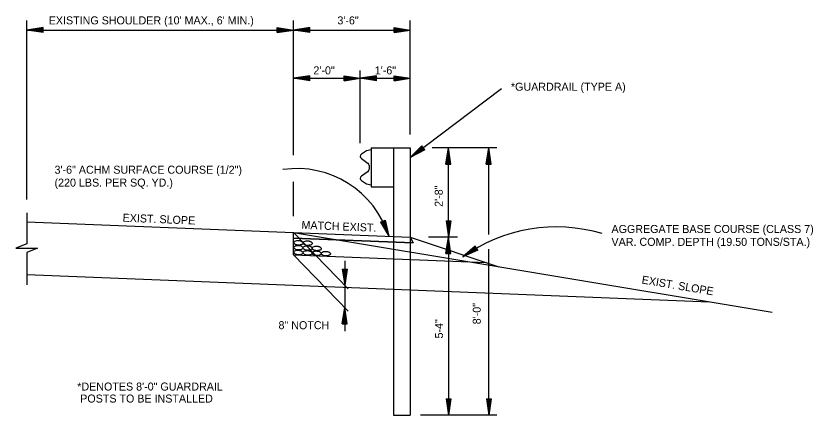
# Model space of a CAD drawing. Extents: x 1374136 to 1374281, y 380549 to 380948.
# Drawn here: x 1374137.7 to 1374197.5, y 380742 to 380771.9 of the extents above; entities that cross this region are included whole.
import ezdxf

# ---------------------------------------------------------------- set-up
doc = ezdxf.new("R2010")
doc.units = 0
for name, color, linetype in [('C-ANNO-TEXT', 7, 'Continuous'), ('Default', 7, 'Continuous'), ('R_Draft', 7, 'Continuous')]:
    doc.layers.add(name, color=color, linetype=linetype)

msp = doc.modelspace()

# ---------------------------------------------------------------- linework, layer by layer
at = {"layer": 'C-ANNO-TEXT'}
msp.add_lwpolyline([(1374138.56, 380757.182), (1374138.56, 380754.852), (1374137.749, 380754.528), (1374139.371, 380754.528), (1374138.56, 380754.205), (1374138.56, 380751.78)], dxfattribs=at)
at = {"layer": 'Default'}
for p, q in [((1374138.56, 380758.166), (1374138.56, 380771.592)), ((1374139.777, 380771.05), (1374138.56, 380770.867)), ((1374139.777, 380770.684), (1374139.777, 380771.05)), ((1374157.342, 380770.684), (1374157.343, 380771.05)), ((1374157.343, 380771.05), (1374158.56, 380770.867)), ((1374158.56, 380761.489), (1374158.56, 380771.592)), ((1374159.777, 380771.05), (1374158.56, 380770.867)), ((1374159.777, 380770.684), (1374159.777, 380771.05)), ((1374166.092, 380770.684), (1374166.093, 380771.05)), ((1374166.093, 380771.05), (1374167.31, 380770.867)), ((1374167.31, 380763.044), (1374167.31, 380771.592)), ((1374138.56, 380770.867), (1374158.56, 380770.867)), ((1374139.777, 380770.684), (1374138.56, 380770.867)), ((1374139.777, 380771.019), (1374138.764, 380770.867)), ((1374139.777, 380770.715), (1374138.764, 380770.867)), ((1374139.777, 380770.987), (1374138.973, 380770.867)), ((1374139.777, 380770.747), (1374138.973, 380770.867)), ((1374139.777, 380770.958), (1374139.177, 380770.868)), ((1374139.777, 380770.776), (1374139.177, 380770.868)), ((1374139.777, 380770.927), (1374139.381, 380770.868)), ((1374139.777, 380770.807), (1374139.381, 380770.868)), ((1374139.777, 380770.895), (1374139.585, 380770.868)), ((1374139.777, 380770.839), (1374139.585, 380770.868)), ((1374157.342, 380770.927), (1374157.739, 380770.868)), ((1374157.342, 380770.895), (1374157.534, 380770.868)), ((1374157.342, 380770.807), (1374157.739, 380770.868)), ((1374157.342, 380770.776), (1374157.943, 380770.868)), ((1374157.342, 380770.839), (1374157.534, 380770.868)), ((1374157.342, 380770.684), (1374158.56, 380770.867)), ((1374157.342, 380770.747), (1374158.147, 380770.867)), ((1374157.342, 380770.715), (1374158.356, 380770.867)), ((1374157.343, 380771.019), (1374158.356, 380770.867)), ((1374157.343, 380770.987), (1374158.147, 380770.867)), ((1374157.343, 380770.958), (1374157.943, 380770.868)), ((1374158.56, 380770.867), (1374167.31, 380770.867)), ((1374159.777, 380770.684), (1374158.56, 380770.867)), ((1374159.777, 380771.019), (1374158.764, 380770.867)), ((1374159.777, 380770.715), (1374158.764, 380770.867)), ((1374159.777, 380770.987), (1374158.973, 380770.867)), ((1374159.777, 380770.747), (1374158.973, 380770.867)), ((1374159.777, 380770.958), (1374159.177, 380770.868)), ((1374159.777, 380770.776), (1374159.177, 380770.868)), ((1374159.777, 380770.927), (1374159.381, 380770.868)), ((1374159.777, 380770.807), (1374159.381, 380770.868)), ((1374159.777, 380770.895), (1374159.585, 380770.868)), ((1374159.777, 380770.839), (1374159.585, 380770.868)), ((1374166.092, 380770.927), (1374166.489, 380770.868)), ((1374166.092, 380770.895), (1374166.284, 380770.868)), ((1374166.092, 380770.807), (1374166.489, 380770.868)), ((1374166.092, 380770.776), (1374166.693, 380770.868)), ((1374166.092, 380770.839), (1374166.284, 380770.868)), ((1374166.092, 380770.684), (1374167.31, 380770.867)), ((1374166.092, 380770.747), (1374166.897, 380770.867)), ((1374166.092, 380770.715), (1374167.106, 380770.867)), ((1374166.093, 380771.019), (1374167.106, 380770.867)), ((1374166.093, 380770.987), (1374166.897, 380770.867)), ((1374166.093, 380770.958), (1374166.693, 380770.868)), ((1374163.56, 380762.404), (1374163.56, 380767.848)), ((1374159.777, 380767.439), (1374158.56, 380767.256)), ((1374158.56, 380767.256), (1374163.56, 380767.256)), ((1374159.777, 380767.073), (1374158.56, 380767.256)), ((1374159.777, 380767.408), (1374158.764, 380767.256)), ((1374159.777, 380767.104), (1374158.764, 380767.256)), ((1374159.777, 380767.376), (1374158.973, 380767.256)), ((1374159.777, 380767.136), (1374158.973, 380767.256)), ((1374159.777, 380767.347), (1374159.177, 380767.257)), ((1374159.777, 380767.165), (1374159.177, 380767.257)), ((1374159.777, 380767.316), (1374159.381, 380767.257)), ((1374159.777, 380767.196), (1374159.381, 380767.257)), ((1374159.777, 380767.284), (1374159.585, 380767.257)), ((1374159.777, 380767.228), (1374159.585, 380767.257)), ((1374159.777, 380767.073), (1374159.777, 380767.439)), ((1374162.342, 380767.073), (1374162.343, 380767.439)), ((1374162.342, 380767.316), (1374162.739, 380767.257)), ((1374162.342, 380767.284), (1374162.534, 380767.257)), ((1374162.342, 380767.196), (1374162.739, 380767.257)), ((1374162.342, 380767.165), (1374162.943, 380767.257)), ((1374162.342, 380767.228), (1374162.534, 380767.257)), ((1374162.342, 380767.073), (1374163.56, 380767.256)), ((1374162.342, 380767.136), (1374163.147, 380767.256)), ((1374162.342, 380767.104), (1374163.356, 380767.256)), ((1374162.343, 380767.439), (1374163.56, 380767.256)), ((1374162.343, 380767.408), (1374163.356, 380767.256)), ((1374162.343, 380767.376), (1374163.147, 380767.256)), ((1374162.343, 380767.347), (1374162.943, 380767.257)), ((1374164.777, 380767.439), (1374163.56, 380767.256)), ((1374163.56, 380767.256), (1374167.31, 380767.256)), ((1374164.777, 380767.073), (1374163.56, 380767.256)), ((1374164.777, 380767.408), (1374163.764, 380767.256)), ((1374164.777, 380767.104), (1374163.764, 380767.256)), ((1374164.777, 380767.376), (1374163.973, 380767.256)), ((1374164.777, 380767.136), (1374163.973, 380767.256)), ((1374164.777, 380767.347), (1374164.177, 380767.257)), ((1374164.777, 380767.165), (1374164.177, 380767.257)), ((1374164.777, 380767.316), (1374164.381, 380767.257)), ((1374164.777, 380767.196), (1374164.381, 380767.257)), ((1374164.777, 380767.284), (1374164.585, 380767.257)), ((1374164.777, 380767.228), (1374164.585, 380767.257)), ((1374164.777, 380767.073), (1374164.777, 380767.439)), ((1374166.092, 380767.073), (1374166.093, 380767.439)), ((1374166.092, 380767.316), (1374166.489, 380767.257)), ((1374166.092, 380767.284), (1374166.284, 380767.257)), ((1374166.092, 380767.196), (1374166.489, 380767.257)), ((1374166.092, 380767.165), (1374166.693, 380767.257)), ((1374166.092, 380767.228), (1374166.284, 380767.257)), ((1374166.092, 380767.073), (1374167.31, 380767.256)), ((1374166.092, 380767.136), (1374166.897, 380767.256)), ((1374166.092, 380767.104), (1374167.106, 380767.256)), ((1374166.093, 380767.439), (1374167.31, 380767.256)), ((1374166.093, 380767.408), (1374167.106, 380767.256)), ((1374166.093, 380767.376), (1374166.897, 380767.256)), ((1374166.093, 380767.347), (1374166.693, 380767.257)), ((1374167.31, 380761.317), (1374174.155, 380766.49)), ((1374168.172, 380762.195), (1374167.31, 380761.317)), ((1374168.193, 380762.172), (1374167.471, 380761.437)), ((1374168.213, 380762.144), (1374167.644, 380761.57)), ((1374168.226, 380762.119), (1374167.804, 380761.69)), ((1374168.246, 380762.099), (1374167.965, 380761.813)), ((1374168.39, 380761.907), (1374168.172, 380762.195)), ((1374164.021, 380761.815), (1374163.645, 380761.563)), ((1374164.385, 380761.886), (1374164.021, 380761.815)), ((1374164.385, 380762.044), (1374167.31, 380762.044)), ((1374164.385, 380762.044), (1374164.385, 380759.119)), ((1374166.06, 380762.044), (1374166.06, 380742.028)), ((1374167.31, 380762.044), (1374167.31, 380742.028)), ((1374168.39, 380761.907), (1374167.31, 380761.317)), ((1374168.374, 380761.929), (1374167.471, 380761.437)), ((1374168.352, 380761.955), (1374167.644, 380761.57)), ((1374168.334, 380761.98), (1374167.804, 380761.69)), ((1374168.313, 380762.006), (1374167.965, 380761.813)), ((1374168.264, 380762.073), (1374168.129, 380761.937)), ((1374168.3, 380762.033), (1374168.129, 380761.937)), ((1374173.788, 380762.044), (1374168.949, 380762.044)), ((1374169.984, 380760.827), (1374170.167, 380762.044)), ((1374170.011, 380760.826), (1374170.165, 380761.842)), ((1374170.045, 380760.828), (1374170.166, 380761.625)), ((1374170.315, 380760.823), (1374170.165, 380761.842)), ((1374170.28, 380760.824), (1374170.166, 380761.625)), ((1374170.167, 380755.353), (1374170.167, 380762.044)), ((1374170.345, 380760.826), (1374170.167, 380762.044)), ((1374173.007, 380760.827), (1374173.19, 380762.044)), ((1374173.034, 380760.826), (1374173.188, 380761.842)), ((1374173.068, 380760.828), (1374173.189, 380761.625)), ((1374173.338, 380760.823), (1374173.188, 380761.842)), ((1374173.303, 380760.824), (1374173.189, 380761.625)), ((1374173.368, 380760.826), (1374173.19, 380762.044)), ((1374173.19, 380755.548), (1374173.19, 380762.044)), ((1374163.642, 380761.243), (1374164.154, 380760.884)), ((1374170.076, 380760.827), (1374170.165, 380761.425)), ((1374170.109, 380760.828), (1374170.166, 380761.222)), ((1374170.139, 380760.822), (1374170.165, 380761.017)), ((1374170.252, 380760.829), (1374170.165, 380761.425)), ((1374170.192, 380760.827), (1374170.165, 380761.017)), ((1374170.224, 380760.825), (1374170.166, 380761.222)), ((1374173.099, 380760.827), (1374173.189, 380761.425)), ((1374173.133, 380760.828), (1374173.189, 380761.222)), ((1374173.162, 380760.822), (1374173.189, 380761.017)), ((1374173.275, 380760.829), (1374173.189, 380761.425)), ((1374173.248, 380760.825), (1374173.189, 380761.222)), ((1374173.216, 380760.827), (1374173.189, 380761.017)), ((1374164.237, 380760.725), (1374164.237, 380760.581)), ((1374164.237, 380760.581), (1374164.237, 380760.437)), ((1374169.984, 380760.827), (1374170.345, 380760.826)), ((1374173.007, 380760.827), (1374173.368, 380760.826)), ((1374164.154, 380760.278), (1374163.642, 380759.919)), ((1374158.56, 380756.926), (1374158.56, 380759.488)), ((1374163.645, 380759.599), (1374164.021, 380759.347)), ((1374164.021, 380759.347), (1374164.385, 380759.276)), ((1374164.385, 380759.119), (1374166.06, 380759.119)), ((1374138.56, 380756.503), (1374158.56, 380755.703)), ((1374165.081, 380756.475), (1374165.419, 380756.615)), ((1374165.081, 380756.475), (1374165.711, 380755.417)), ((1374165.108, 380756.489), (1374165.634, 380755.607)), ((1374165.141, 380756.496), (1374165.555, 380755.802)), ((1374165.167, 380756.51), (1374165.48, 380755.986)), ((1374165.195, 380756.521), (1374165.401, 380756.179)), ((1374165.224, 380756.534), (1374165.321, 380756.366)), ((1374165.274, 380756.554), (1374165.321, 380756.366)), ((1374165.305, 380756.567), (1374165.401, 380756.179)), ((1374165.336, 380756.578), (1374165.48, 380755.986)), ((1374165.362, 380756.589), (1374165.555, 380755.802)), ((1374165.393, 380756.599), (1374165.634, 380755.607)), ((1374165.419, 380756.615), (1374165.711, 380755.417)), ((1374169.99, 380756.571), (1374170.167, 380755.353)), ((1374169.99, 380756.571), (1374170.352, 380756.57)), ((1374170.017, 380756.572), (1374170.166, 380755.555)), ((1374170.052, 380756.569), (1374170.168, 380755.772)), ((1374170.083, 380756.57), (1374170.169, 380755.973)), ((1374170.116, 380756.569), (1374170.17, 380756.175)), ((1374170.145, 380756.575), (1374170.171, 380756.38)), ((1374170.321, 380756.573), (1374170.166, 380755.555)), ((1374170.352, 380756.57), (1374170.167, 380755.353)), ((1374170.286, 380756.572), (1374170.168, 380755.772)), ((1374170.259, 380756.568), (1374170.169, 380755.973)), ((1374170.231, 380756.571), (1374170.17, 380756.175)), ((1374170.199, 380756.57), (1374170.171, 380756.38)), ((1374162.649, 380751.485), (1374158.56, 380755.703)), ((1374158.56, 380755.703), (1374167.31, 380755.353)), ((1374158.56, 380755.703), (1374194.432, 380749.725)), ((1374158.56, 380754.028), (1374158.56, 380755.703)), ((1374158.56, 380755.278), (1374167.527, 380754.92)), ((1374167.31, 380755.353), (1374173.96, 380753.137)), ((1374167.31, 380755.353), (1374167.527, 380754.92)), ((1374170.858, 380755.353), (1374168.68, 380755.353)), ((1374169.984, 380754.137), (1374170.167, 380755.353)), ((1374170.011, 380754.136), (1374170.165, 380755.152)), ((1374170.045, 380754.138), (1374170.166, 380754.935)), ((1374170.315, 380754.133), (1374170.165, 380755.152)), ((1374170.28, 380754.134), (1374170.166, 380754.935)), ((1374170.167, 380755.353), (1374170.167, 380742.028)), ((1374170.345, 380754.136), (1374170.167, 380755.353)), ((1374170.076, 380754.137), (1374170.165, 380754.734)), ((1374170.109, 380754.138), (1374170.166, 380754.532)), ((1374170.139, 380754.132), (1374170.165, 380754.327)), ((1374170.252, 380754.138), (1374170.165, 380754.734)), ((1374170.192, 380754.137), (1374170.165, 380754.327)), ((1374170.224, 380754.135), (1374170.166, 380754.532)), ((1374172.175, 380754.683), (1374171.251, 380753.869)), ((1374172.375, 380754.374), (1374171.251, 380753.869)), ((1374172.193, 380754.655), (1374171.424, 380753.977)), ((1374172.356, 380754.4), (1374171.424, 380753.977)), ((1374172.209, 380754.629), (1374171.598, 380754.093)), ((1374172.338, 380754.426), (1374171.598, 380754.093)), ((1374172.225, 380754.605), (1374171.768, 380754.203)), ((1374172.322, 380754.45), (1374171.768, 380754.203)), ((1374172.241, 380754.577), (1374171.94, 380754.314)), ((1374172.306, 380754.476), (1374171.94, 380754.314)), ((1374172.259, 380754.551), (1374172.114, 380754.425)), ((1374172.29, 380754.504), (1374172.114, 380754.425)), ((1374172.375, 380754.374), (1374172.175, 380754.683)), ((1374173.19, 380742.028), (1374173.19, 380754.445)), ((1374162.649, 380749.81), (1374158.56, 380754.028)), ((1374158.56, 380754.028), (1374173.02, 380753.45)), ((1374169.984, 380754.137), (1374170.345, 380754.136)), ((1374162.392, 380753.584), (1374162.392, 380748.308)), ((1374138.56, 380752.553), (1374189.744, 380750.506)), ((1374162.216, 380752.968), (1374162.392, 380751.75)), ((1374162.216, 380752.968), (1374162.577, 380752.967)), ((1374162.243, 380752.968), (1374162.391, 380751.951)), ((1374162.277, 380752.966), (1374162.394, 380752.169)), ((1374162.308, 380752.967), (1374162.394, 380752.369)), ((1374162.341, 380752.966), (1374162.396, 380752.571)), ((1374162.371, 380752.971), (1374162.396, 380752.776)), ((1374162.547, 380752.969), (1374162.391, 380751.951)), ((1374162.577, 380752.967), (1374162.392, 380751.75)), ((1374162.512, 380752.969), (1374162.394, 380752.169)), ((1374162.484, 380752.964), (1374162.394, 380752.369)), ((1374162.456, 380752.968), (1374162.396, 380752.571)), ((1374162.424, 380752.966), (1374162.396, 380752.776)), ((1374162.209, 380748.858), (1374162.392, 380750.075)), ((1374162.236, 380748.857), (1374162.39, 380749.873)), ((1374162.27, 380748.859), (1374162.391, 380749.656)), ((1374162.54, 380748.854), (1374162.39, 380749.873)), ((1374162.505, 380748.855), (1374162.391, 380749.656)), ((1374162.57, 380748.857), (1374162.392, 380750.075)), ((1374162.301, 380748.858), (1374162.39, 380749.456)), ((1374162.334, 380748.859), (1374162.391, 380749.253)), ((1374162.364, 380748.853), (1374162.391, 380749.048)), ((1374162.477, 380748.86), (1374162.39, 380749.456)), ((1374162.449, 380748.857), (1374162.391, 380749.253)), ((1374162.418, 380748.858), (1374162.391, 380749.048)), ((1374162.209, 380748.858), (1374162.57, 380748.857)), ((1374169.99, 380743.246), (1374170.167, 380742.028)), ((1374169.99, 380743.246), (1374170.352, 380743.245)), ((1374170.017, 380743.247), (1374170.166, 380742.23)), ((1374170.052, 380743.244), (1374170.168, 380742.447)), ((1374170.083, 380743.245), (1374170.169, 380742.648)), ((1374170.116, 380743.244), (1374170.17, 380742.85)), ((1374170.145, 380743.25), (1374170.171, 380743.055)), ((1374170.321, 380743.248), (1374170.166, 380742.23)), ((1374170.352, 380743.245), (1374170.167, 380742.028)), ((1374170.286, 380743.247), (1374170.168, 380742.447)), ((1374170.259, 380743.243), (1374170.169, 380742.648)), ((1374170.231, 380743.246), (1374170.17, 380742.85)), ((1374170.199, 380743.245), (1374170.171, 380743.055)), ((1374173.014, 380743.246), (1374173.19, 380742.028)), ((1374173.014, 380743.246), (1374173.375, 380743.245)), ((1374173.041, 380743.247), (1374173.189, 380742.23)), ((1374173.075, 380743.244), (1374173.192, 380742.447)), ((1374173.106, 380743.245), (1374173.192, 380742.648)), ((1374173.139, 380743.244), (1374173.194, 380742.85)), ((1374173.169, 380743.25), (1374173.194, 380743.055)), ((1374173.345, 380743.248), (1374173.189, 380742.23)), ((1374173.375, 380743.245), (1374173.19, 380742.028)), ((1374173.31, 380743.247), (1374173.192, 380742.447)), ((1374173.282, 380743.243), (1374173.192, 380742.648)), ((1374173.254, 380743.246), (1374173.194, 380742.85)), ((1374173.223, 380743.245), (1374173.194, 380743.055)), ((1374173.788, 380742.028), (1374168.084, 380742.028))]:
    msp.add_line(p, q, dxfattribs=at)
msp.add_lwpolyline([(1374158.56, 380755.278), (1374158.56, 380755.703), (1374167.31, 380755.353), (1374167.527, 380754.92)], close=True, dxfattribs=at)
for centre, radius, start, end in [((1374163.755, 380761.402), 0.195, 124.15804, 234.74711), ((1374158.802, 380753.252), 7.24, 17.40271, 98.21594), ((1374164.042, 380760.725), 0.195, 360, 54.74711), ((1374164.042, 380760.437), 0.195, 305.25289, 0), ((1374163.755, 380759.76), 0.195, 125.25289, 235.84196), ((1374178.254, 380744.097), 12.021, 73.3815, 125.63175)]:
    msp.add_arc(centre, radius, start, end, dxfattribs=at)
for points in [[(1374158.931, 380755.102), (1374158.811, 380755.1), (1374158.664, 380755.051), (1374158.594, 380754.987), (1374158.583, 380754.943), (1374158.618, 380754.87), (1374158.661, 380754.836), (1374158.737, 380754.798), (1374158.857, 380754.764), (1374158.915, 380754.759), (1374159.006, 380754.765), (1374159.105, 380754.782), (1374159.182, 380754.81), (1374159.252, 380754.867), (1374159.264, 380754.911), (1374159.243, 380754.976), (1374159.189, 380755.021), (1374159.138, 380755.058), (1374159.059, 380755.085), (1374159.008, 380755.097), (1374158.931, 380755.102)], [(1374159.617, 380755.074), (1374159.497, 380755.072), (1374159.35, 380755.024), (1374159.28, 380754.959), (1374159.269, 380754.916), (1374159.304, 380754.842), (1374159.347, 380754.809), (1374159.423, 380754.771), (1374159.543, 380754.736), (1374159.601, 380754.732), (1374159.692, 380754.738), (1374159.791, 380754.754), (1374159.868, 380754.782), (1374159.938, 380754.84), (1374159.95, 380754.883), (1374159.929, 380754.949), (1374159.875, 380754.994), (1374159.824, 380755.031), (1374159.745, 380755.058), (1374159.694, 380755.069), (1374159.617, 380755.074)], [(1374158.931, 380754.737), (1374158.811, 380754.735), (1374158.664, 380754.686), (1374158.594, 380754.622), (1374158.583, 380754.578), (1374158.618, 380754.505), (1374158.661, 380754.471), (1374158.737, 380754.433), (1374158.857, 380754.399), (1374158.915, 380754.394), (1374159.006, 380754.4), (1374159.105, 380754.417), (1374159.182, 380754.445), (1374159.252, 380754.502), (1374159.264, 380754.546), (1374159.243, 380754.611), (1374159.189, 380754.656), (1374159.138, 380754.693), (1374159.059, 380754.72), (1374159.008, 380754.732), (1374158.931, 380754.737)], [(1374158.931, 380754.372), (1374158.811, 380754.37), (1374158.664, 380754.321), (1374158.594, 380754.257), (1374158.583, 380754.213), (1374158.618, 380754.14), (1374158.661, 380754.106), (1374158.737, 380754.068), (1374158.857, 380754.034), (1374158.915, 380754.029), (1374159.006, 380754.035), (1374159.105, 380754.052), (1374159.182, 380754.08), (1374159.252, 380754.137), (1374159.264, 380754.181), (1374159.243, 380754.247), (1374159.189, 380754.291), (1374159.138, 380754.328), (1374159.059, 380754.355), (1374159.008, 380754.367), (1374158.931, 380754.372)], [(1374159.617, 380754.709), (1374159.497, 380754.707), (1374159.35, 380754.659), (1374159.28, 380754.594), (1374159.269, 380754.551), (1374159.304, 380754.477), (1374159.347, 380754.444), (1374159.423, 380754.406), (1374159.543, 380754.371), (1374159.601, 380754.367), (1374159.692, 380754.373), (1374159.791, 380754.389), (1374159.868, 380754.417), (1374159.938, 380754.475), (1374159.95, 380754.518), (1374159.929, 380754.584), (1374159.875, 380754.629), (1374159.824, 380754.666), (1374159.745, 380754.693), (1374159.694, 380754.704), (1374159.617, 380754.709)], [(1374159.617, 380754.344), (1374159.497, 380754.342), (1374159.35, 380754.294), (1374159.28, 380754.229), (1374159.269, 380754.186), (1374159.304, 380754.112), (1374159.347, 380754.079), (1374159.423, 380754.041), (1374159.543, 380754.006), (1374159.601, 380754.002), (1374159.692, 380754.008), (1374159.791, 380754.024), (1374159.868, 380754.052), (1374159.938, 380754.11), (1374159.95, 380754.153), (1374159.929, 380754.219), (1374159.875, 380754.264), (1374159.824, 380754.301), (1374159.745, 380754.328), (1374159.694, 380754.339), (1374159.617, 380754.344)], [(1374160.303, 380754.682), (1374160.183, 380754.68), (1374160.036, 380754.631), (1374159.966, 380754.567), (1374159.955, 380754.523), (1374159.99, 380754.45), (1374160.033, 380754.416), (1374160.109, 380754.379), (1374160.229, 380754.344), (1374160.287, 380754.339), (1374160.378, 380754.345), (1374160.477, 380754.362), (1374160.554, 380754.39), (1374160.624, 380754.447), (1374160.636, 380754.491), (1374160.615, 380754.557), (1374160.561, 380754.601), (1374160.511, 380754.638), (1374160.431, 380754.665), (1374160.38, 380754.677), (1374160.303, 380754.682)], [(1374160.303, 380754.317), (1374160.183, 380754.315), (1374160.036, 380754.266), (1374159.966, 380754.202), (1374159.955, 380754.158), (1374159.99, 380754.085), (1374160.033, 380754.051), (1374160.109, 380754.014), (1374160.229, 380753.979), (1374160.287, 380753.974), (1374160.378, 380753.98), (1374160.477, 380753.997), (1374160.554, 380754.025), (1374160.624, 380754.082), (1374160.636, 380754.126), (1374160.615, 380754.192), (1374160.561, 380754.236), (1374160.511, 380754.273), (1374160.431, 380754.3), (1374160.38, 380754.312), (1374160.303, 380754.317)], [(1374160.989, 380754.289), (1374160.869, 380754.288), (1374160.723, 380754.239), (1374160.652, 380754.174), (1374160.641, 380754.131), (1374160.676, 380754.057), (1374160.719, 380754.024), (1374160.795, 380753.986), (1374160.915, 380753.951), (1374160.973, 380753.947), (1374161.064, 380753.953), (1374161.163, 380753.969), (1374161.24, 380753.997), (1374161.31, 380754.055), (1374161.322, 380754.098), (1374161.301, 380754.164), (1374161.247, 380754.209), (1374161.197, 380754.246), (1374161.117, 380754.273), (1374161.066, 380754.284), (1374160.989, 380754.289)]]:
    msp.add_spline(points, degree=3, dxfattribs=at)
at = {"layer": 'R_Draft'}
msp.add_line((1374166.06, 380742.028), (1374167.31, 380742.028), dxfattribs=at)

# ---------------------------------------------------------------- texts
at = {"layer": 'Default'}
for s, p in [("EXISTING SHOULDER (10' MAX., 6' MIN.)", (1374140.207, 380771.292)), ('3\'-6"', (1374161.846, 380771.292)), ('2\'-0"', (1374160.049, 380767.548)), ('1\'-6"', (1374164.647, 380767.548)), ('*GUARDRAIL (TYPE A)', (1374174.855, 380766.323)), ('3\'-6" ACHM SURFACE COURSE (1/2")', (1374140.642, 380760.106)), ('(220 LBS. PER SQ. YD.)', (1374140.642, 380759.141)), ('AGGREGATE BASE COURSE (CLASS 7)', (1374182.395, 380755.667)), ('VAR. COMP. DEPTH (19.50 TONS/STA.)', (1374182.395, 380754.703)), ('8" NOTCH', (1374157.432, 380748.46)), ('*DENOTES 8\'-0" GUARDRAIL', (1374142.344, 380743.863)), (' POSTS TO BE INSTALLED', (1374142.344, 380742.963))]:
    msp.add_text(s, height=0.6, dxfattribs=at).set_placement(p)
for s, rotation, p in [('2\'-8"', 90, (1374169.744, 380757.624)), ('EXIST. SLOPE', 357.70939, (1374145.737, 380756.517)), ('MATCH EXIST.', 357.70939, (1374159.146, 380755.98)), ('EXIST. SLOPE', 350.53768, (1374184.627, 380751.886)), ('8\'-0"', 90, (1374172.594, 380748.826)), ('5-4"', 90, (1374169.761, 380747.763))]:
    msp.add_text(s, height=0.6, rotation=rotation, dxfattribs=at).set_placement(p)

doc.saveas('drawing.dxf')
